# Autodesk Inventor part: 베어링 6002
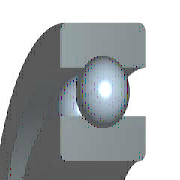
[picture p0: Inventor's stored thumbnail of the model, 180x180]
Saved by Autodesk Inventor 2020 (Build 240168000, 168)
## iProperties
Created: 2012-02
Part Number: 베어링 6002
Material: 강철, 연강
Description: 깊은 그루브 볼 베어링
Document SubType Name: Modeling
Standard: KS B 2023
Designer: mduedu
Standards Organization: KS
Language: ko-KR
Size Designation: 6002 - 15 x 32 x 9
Categories: <MemberInstance><Categories><Category DisplayName="샤프트 부품" InternalName="7f7aeb1f-a693-4053-b835-cee3144e0d98" Mnemonic="SHFT"><Category DisplayName="베어링" Inter
Density: 7.86 g/cm^3
Mass: 29.8124 g
Surface Area: 39.9079 cm^2
Volume: 3.79293 cm^3
Appearance: 분홍색
IsCustomPart: 1
Author: mduedu
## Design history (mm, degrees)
sketch "스케치" dims "d0" = 4.42 (= -0.26 x WD + 0.26 x BD)
  geometry: L1 (2.29, 11.75)-(6.71, 11.75); L2 (4.5, 11.75)-(4.5, 9.54); L3 (4.5, 11.75)-(4.5, 13.96); L4 (2.858, 10.271)-(0, 10.271); L5 (0, 7.5)-(9, 7.5); L6 (2.858, 13.229)-(0, 13.229); L7 (0, 16)-(9, 16); L8 (9, 7.5)-(9, 10.271); L9 (6.142, 10.271)-(9, 10.271); L10 (6.142, 13.229)-(9, 13.229); L11 (9, 16)-(9, 13.229); L12 (-1.4, 0)-(8.4, 0) reference; L13 (0, -0.3)-(0, 5.3) reference
  constraints: 22 end point, 4 point on line, 2 collinear, 2 perpendicular, 2 symmetric about line, 1 midpoint, 1 parallel, 14 other
  dimensions: "d9" = 15 diameter of L5 L12 (= WD); "d11" = 32 diameter of L7 L12 (= BD); "d12" = 9 distance between parallel lines of L8 L13 (= KB); "d13" = 20.542 diameter of L9 L12 (= 0.326 x BD + 0.674 x WD)
revolve "본체" stored, may be unused: angle "d6" = 90 deg
revolve "볼" stored, may be unused: angle "d7" = 90 deg
pattern_circular "IDS_ARRAYBALL[SIMPL:T]" dims angle "d3" = 360 deg
body "Solid1"
fillet "모깎기1" dims "d1" = 0.3 (= KRS)
other parameters: "WD" = 15 [user parameter; used in 5 equation terms], "BD" = 32 [user parameter; used in 5 equation terms], "KB" = 9 [user parameter; used in 1 equation term], "KRS" = 0.3 [user parameter; used in 1 equation term], "d4" = 0, "d5" = 0, "d8" = 0, "d14" = 0, "d15" = 0, "BBA" = 0 [user parameter], "BC0" = 2850000 [user parameter], "BC" = 5590000 [user parameter], "BR" = 16 (= 0.5 x BD) [user parameter], "WR" = 7.5 (= 0.5 x WD) [user parameter]
